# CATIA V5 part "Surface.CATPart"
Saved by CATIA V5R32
Part number: Part1
Bounding box of the stored display mesh (mm): x -50 to 50, y 0 to 200, z 0 to 79.597
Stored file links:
  D:\PROJECTS\Project 2022\CATIA V5 6R 2022\Resources\Part Files\c16_catia_v5_6r2022_prt\Point Surface Joint-(Fig16-46)\Surface.CATPart
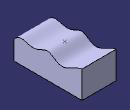
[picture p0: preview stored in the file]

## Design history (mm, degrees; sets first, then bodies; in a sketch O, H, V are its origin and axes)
Body1 (main body)
  Sketch1 on yz-plane, origin (0, 0, 0), H (0, 1, 0), V (0, 0, 1)
    spline S1 through (0, 52.7587) (16.6889, 67.1156) (74.2459, 65.3633) (97.6382, 74.1545) (129.8025, 59.0839) (168.2327, 66.2006) (200, 79.5967)
    line L1 (0, 52.7587) -> (0, 0)
    point P1 (0, 52.7587)
    point P2 (0, 0)
    line L2 (0, 0) -> (200, 0)
    line L3 (200, 0) -> (200, 79.5967)
    point P4 (200, 79.5967)
    point P5 (0, 52.7587)
    point P6 (200, 79.5967)
    length L2 = 200
    coincidence: P5 P1, P2 H, P6 P4, L1 V
    vertical: L1 V, L3 V
    horizontal: L2 H
  Pad1: profile Sketch1, direction (1, 0, 0), length 50, mirrored extent
  Point1: type OnSurface, Support face of Pad1 from Sketch1.S1, Length 0, Direction (0.8882, 0.2225, -0.4019)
